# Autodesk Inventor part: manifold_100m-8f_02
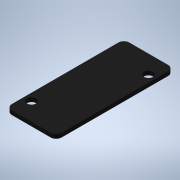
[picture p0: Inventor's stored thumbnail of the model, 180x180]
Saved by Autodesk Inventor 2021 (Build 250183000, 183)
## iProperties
Created: 2021-02
Part Number: manifold_100m-8f_02
Checked By: TraceParts S.A.
Material: Genérico
Catalog Web Link: www.traceparts.com
Document SubType Name: Modeling
Designer: TraceParts
Density: 1 g/cm^3
Appearance: Por defecto
Company: TraceParts S.A.
Author: TraceParts
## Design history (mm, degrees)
feature "manifold_100m-8f_02.ipt"
body "Solid1"
